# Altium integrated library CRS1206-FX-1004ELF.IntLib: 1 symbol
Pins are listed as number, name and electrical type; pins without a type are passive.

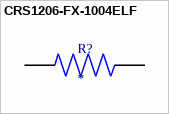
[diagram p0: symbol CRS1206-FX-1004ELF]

## CRS1206-FX-1004ELF
designator R?
RESISTOR, THICK FILM, 1M, 1%, 1206; MP: CRS1206-FX-1004ELF
footprint RESC3116X65N
pins: 1, 2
